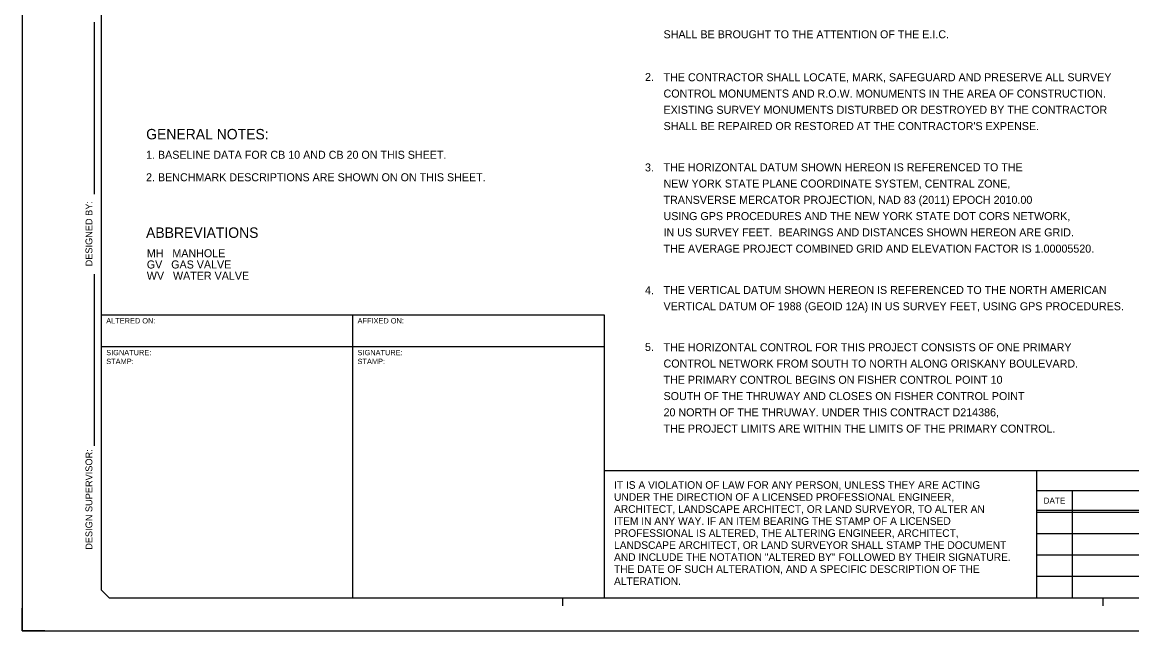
# Model space of a CAD drawing. Extents: x 359002 to 1164845, y 1141798 to 1525369.
# Drawn here: x 1163485 to 1164183, y 1141798 to 1142181 of the extents above; entities that cross this region are included whole.
import ezdxf

# ---------------------------------------------------------------- set-up
doc = ezdxf.new("R2010")
doc.units = 0
for name, color, linetype in [('Default', 7, 'Continuous'), ('Manuscript', 7, 'Continuous'), ('Plan Sheet Info_', 7, 'Continuous'), ('SHEET_BORDER', 7, 'Continuous'), ('SHEET_BORDER_EDGE', 7, 'Continuous'), ('SHEET_BORDER_STAMPBOX', 7, 'Continuous'), ('SHEET_BORDER_TEXT', 7, 'Continuous')]:
    doc.layers.add(name, color=color, linetype=linetype)

msp = doc.modelspace()

# ---------------------------------------------------------------- linework, layer by layer
at = {"layer": 'SHEET_BORDER'}
for p, q in [((1163530.18, 1142072.44), (1163530.18, 1142180.5)), ((1163530.18, 1141914.1), (1163530.18, 1142022.02)), ((1164123.01, 1141818.28), (1164123.01, 1141898.28)), ((1164794.64, 1141898.28), (1164123.01, 1141898.28)), ((1164123.01, 1141818.28), (1164123.01, 1141898.28)), ((1164362.76, 1141885.8), (1164123.01, 1141885.8)), ((1164362.76, 1141885.8), (1164123.01, 1141885.8)), ((1164362.76, 1141873.32), (1164123.01, 1141873.32)), ((1164362.76, 1141873.32), (1164123.01, 1141873.32)), ((1164362.76, 1141872.04), (1164123.01, 1141872.04)), ((1164362.76, 1141858.6), (1164123.01, 1141858.6)), ((1164362.76, 1141845.16), (1164123.01, 1141845.16)), ((1164362.76, 1141831.72), (1164123.01, 1141831.72)), ((1163824.64, 1141818.28), (1163824.64, 1141813.28)), ((1164164.64, 1141818.28), (1164164.64, 1141813.28))]:
    msp.add_line(p, q, dxfattribs=at)
msp.add_lwpolyline([(1164794.64, 1141823.28), (1164789.64, 1141818.28), (1163539.64, 1141818.28), (1163534.64, 1141823.28), (1163534.64, 1142652.02), (1163539.64, 1142657.02), (1164789.64, 1142657.02), (1164794.64, 1142652.02)], close=True, dxfattribs=at)
msp.add_lwpolyline([(1164145.51, 1141818.28), (1164145.51, 1141885.8)], dxfattribs=at)
at = {"layer": 'SHEET_BORDER_EDGE'}
msp.add_lwpolyline([(1163484.64, 1141797.65), (1164844.64, 1141797.65), (1164844.64, 1142677.65), (1163484.64, 1142677.65)], close=True, dxfattribs=at)
msp.add_lwpolyline([(1163498.78, 1141797.65), (1163484.64, 1141797.65), (1163484.64, 1141811.79)], dxfattribs=at)
at = {"layer": 'SHEET_BORDER_STAMPBOX'}
for p, q in [((1163534.64, 1141996.4), (1163850.89, 1141996.4)), ((1163692.76, 1141818.28), (1163692.76, 1141996.4)), ((1163850.89, 1141996.4), (1163850.89, 1141818.28)), ((1163850.89, 1141976.4), (1163534.64, 1141976.4)), ((1164123.01, 1141898.28), (1163850.89, 1141898.28))]:
    msp.add_line(p, q, dxfattribs=at)

# ---------------------------------------------------------------- texts
at = {"layer": 'Default'}
for s, p in [('GENERAL NOTES:', (1163562.65, 1142106.83)), ('ABBREVIATIONS', (1163562.58, 1142044.86))]:
    msp.add_text(s, height=6.5617, rotation=360, dxfattribs=at).set_placement(p)
at = {"layer": 'Manuscript'}
for s, height, p in [('SHALL BE BROUGHT TO THE ATTENTION OF THE E.I.C.', 5.0361, (1163888.16, 1142170.42)), ('2.', 5.036, (1163876.49, 1142143.53)), ('THE CONTRACTOR SHALL LOCATE, MARK, SAFEGUARD AND PRESERVE ALL SURVEY', 5.0361, (1163888.16, 1142143.38)), ('CONTROL MONUMENTS AND R.O.W. MONUMENTS IN THE AREA OF CONSTRUCTION.', 5.0361, (1163888.16, 1142133.14)), ('EXISTING SURVEY MONUMENTS DISTURBED OR DESTROYED BY THE CONTRACTOR', 5.0361, (1163888.16, 1142122.9)), ("SHALL BE REPAIRED OR RESTORED AT THE CONTRACTOR'S EXPENSE. ", 5.0361, (1163888.16, 1142112.67)), ('3.', 5.036, (1163876.49, 1142086.66)), ('THE HORIZONTAL DATUM SHOWN HEREON IS REFERENCED TO THE ', 5.0361, (1163888.16, 1142086.75)), ('NEW YORK STATE PLANE COORDINATE SYSTEM, CENTRAL ZONE, ', 5.0361, (1163888.16, 1142076.51)), ('TRANSVERSE MERCATOR PROJECTION, NAD 83 (2011) EPOCH 2010.00', 5.0361, (1163888.16, 1142066.27)), ('USING GPS PROCEDURES AND THE NEW YORK STATE DOT CORS NETWORK,', 5.0361, (1163888.16, 1142056.04)), ('IN US SURVEY FEET.  BEARINGS AND DISTANCES SHOWN HEREON ARE GRID.', 5.0361, (1163888.16, 1142045.8)), ('THE AVERAGE PROJECT COMBINED GRID AND ELEVATION FACTOR IS 1.00005520.', 5.0361, (1163888.16, 1142035.57)), ('4.', 5.036, (1163876.49, 1142009.4)), ('THE VERTICAL DATUM SHOWN HEREON IS REFERENCED TO THE NORTH AMERICAN', 5.0361, (1163888.16, 1142009.56)), ('VERTICAL DATUM OF 1988 (GEOID 12A) IN US SURVEY FEET, USING GPS PROCEDURES.', 5.0361, (1163888.16, 1141999.32)), ('5.', 5.036, (1163876.49, 1141973.71)), ('THE HORIZONTAL CONTROL FOR THIS PROJECT CONSISTS OF ONE PRIMARY', 5.0361, (1163888.16, 1141973.52)), ('CONTROL NETWORK FROM SOUTH TO NORTH ALONG ORISKANY BOULEVARD.', 5.0361, (1163888.16, 1141963.28)), ('THE PRIMARY CONTROL BEGINS ON FISHER CONTROL POINT 10', 5.0361, (1163888.16, 1141953.05)), ('SOUTH OF THE THRUWAY AND CLOSES ON FISHER CONTROL POINT', 5.0361, (1163888.16, 1141942.81)), ('20 NORTH OF THE THRUWAY. UNDER THIS CONTRACT D214386,', 5.0361, (1163888.16, 1141932.58)), ('THE PROJECT LIMITS ARE WITHIN THE LIMITS OF THE PRIMARY CONTROL.', 5.0361, (1163888.16, 1141922.34))]:
    msp.add_text(s, height=height, dxfattribs=at).set_placement(p)
at = {"layer": 'Plan Sheet Info_'}
for s, p in [('1. BASELINE DATA FOR CB 10 AND CB 20 ON THIS SHEET.', (1163562.58, 1142094.61)), ('2. BENCHMARK DESCRIPTIONS ARE SHOWN ON ON THIS SHEET.', (1163562.58, 1142080.47)), ('MH   MANHOLE', (1163563.05, 1142032.66)), ('GV   GAS VALVE', (1163563.05, 1142025.59)), ('WV   WATER VALVE', (1163563.05, 1142018.52))]:
    msp.add_text(s, height=5.0361, rotation=360, dxfattribs=at).set_placement(p)
at = {"layer": 'SHEET_BORDER'}
msp.add_text('DATE', height=3.84, rotation=360, dxfattribs=at).set_placement((1164127.25, 1141877.64))
at = {"layer": 'SHEET_BORDER_STAMPBOX'}
for s, height, p in [('ALTERED ON:', 3.36, (1163537.52, 1141991.01)), ('AFFIXED ON:', 3.36, (1163695.65, 1141991.01)), ('SIGNATURE:', 3.36, (1163537.52, 1141971.01)), ('SIGNATURE:', 3.36, (1163695.65, 1141971.01)), ('STAMP:', 3.36, (1163537.52, 1141965.46)), ('STAMP:', 3.36, (1163695.65, 1141965.46)), ('IT IS A VIOLATION OF LAW FOR ANY PERSON, UNLESS THEY ARE ACTING ', 4.8, (1163857.01, 1141886.99)), ('UNDER THE DIRECTION OF A LICENSED PROFESSIONAL ENGINEER, ', 4.8, (1163857.01, 1141879.43)), ('ARCHITECT, LANDSCAPE ARCHITECT, OR LAND SURVEYOR, TO ALTER AN ', 4.8, (1163857.01, 1141871.87)), ('ITEM IN ANY WAY. IF AN ITEM BEARING THE STAMP OF A LICENSED ', 4.8, (1163857.01, 1141864.31)), ('PROFESSIONAL IS ALTERED, THE ALTERING ENGINEER, ARCHITECT, ', 4.8, (1163857.01, 1141856.74)), ('LANDSCAPE ARCHITECT, OR LAND SURVEYOR SHALL STAMP THE DOCUMENT ', 4.8, (1163857.01, 1141849.18)), ('AND INCLUDE THE NOTATION "ALTERED BY" FOLLOWED BY THEIR SIGNATURE. ', 4.8, (1163857.01, 1141841.62)), ('THE DATE OF SUCH ALTERATION, AND A SPECIFIC DESCRIPTION OF THE ', 4.8, (1163857.01, 1141834.06)), ('ALTERATION.', 4.8, (1163857.01, 1141826.49))]:
    msp.add_text(s, height=height, rotation=360, dxfattribs=at).set_placement(p)
at = {"layer": 'SHEET_BORDER_TEXT'}
for s, p in [('DESIGNED BY:', (1163528.79, 1142026.92)), ('DESIGN SUPERVISOR:', (1163528.79, 1141848.63))]:
    msp.add_text(s, height=4.32, rotation=90, dxfattribs=at).set_placement(p)

doc.saveas('drawing.dxf')
